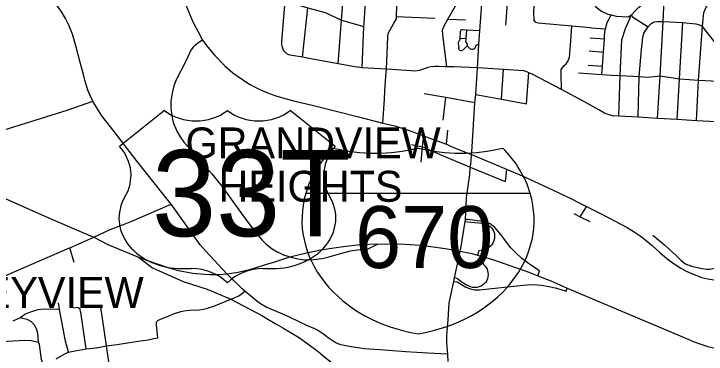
# Model space of a CAD drawing. Extents: x 1755200 to 1902939, y 644115 to 788070.
# Drawn here: x 1808159 to 1819343, y 715838 to 721334 of the extents above; entities that cross this region are included whole.
import ezdxf

# ---------------------------------------------------------------- set-up
doc = ezdxf.new("R2010")
doc.units = 0
for name, color, linetype in [('GM_X_City_Street', 7, 'Continuous'), ('GM_X_Corporation_Text', 7, 'Continuous'), ('GM_X_County_Road', 7, 'Continuous'), ('GM_X_Interchange_Ramps', 7, 'Continuous'), ('GM_X_Interstate_Route', 7, 'Continuous'), ('GM_X_Interstate_Shield', 7, 'Continuous'), ('GM_X_Township_Road', 7, 'Continuous'), ('GM_X_US_Route', 7, 'Continuous'), ('GM_X_US_Shield', 7, 'Continuous')]:
    doc.layers.add(name, color=color, linetype=linetype)

msp = doc.modelspace()

# ---------------------------------------------------------------- linework, layer by layer
at = {"layer": 'GM_X_City_Street'}
for points in [[(1813399, 720526), (1813451, 721233), (1813462, 721370), (1813547, 722431), (1813595, 723417)], [(1813818, 721182), (1813850, 721684), (1813883, 722187), (1813897, 722412), (1813959, 723379)], [(1816584, 721201), (1816564, 721229), (1816558, 721365), (1816571, 721550), (1816588, 721789), (1816595, 721883), (1816650, 722239), (1816678, 722540), (1816697, 722825), (1816713, 723063), (1816708, 723224)], [(1818559, 719644), (1818600, 720335), (1818648, 721210), (1818666, 721565), (1818619, 721791), (1818559, 722124), (1818551, 722245), (1818535, 722548), (1818544, 722781), (1818562, 723136)], [(1816109, 721151), (1816139, 721581), (1816162, 721906), (1816162, 721912), (1816202, 722264), (1816210, 722573), (1816230, 722857)], [(1815152, 720480), (1815091, 720998), (1815081, 721074), (1815119, 721161), (1815168, 721246), (1815293, 721465), (1815313, 721537), (1815344, 722283)], [(1815651, 720462), (1815662, 720643), (1815673, 720842), (1815689, 721058), (1815729, 721639), (1815751, 721965), (1815773, 722298), (1815773, 722298)], [(1809958, 719201), (1809777, 719434), (1809579, 719687), (1809497, 719814), (1809437, 719926), (1809398, 720003), (1809352, 720103), (1809304, 720261), (1809284, 720354), (1809233, 720551), (1809163, 720815), (1809107, 721004), (1809049, 721151), (1808995, 721259), (1808923, 721378), (1808795, 721558)], [(1814173, 720391), (1814173, 720391), (1814178, 720440), (1814200, 720961), (1814207, 721018), (1814300, 721182), (1814340, 721254), (1814342, 721293), (1814343, 721320), (1814356, 721651)], [(1815729, 721639), (1816139, 721581), (1816571, 721550), (1817069, 721516), (1817485, 721487), (1817541, 721482), (1817561, 721450), (1817650, 721377), (1817753, 721330), (1817809, 721316), (1817888, 721295), (1818085, 721284), (1818136, 721316), (1818155, 721285), (1818407, 721123), (1818447, 721175), (1818496, 721204), (1818544, 721213), (1818648, 721210), (1818967, 721193), (1819174, 721175), (1819235, 721155), (1819283, 721130)], [(1817930, 719683), (1817956, 720341), (1817979, 720913), (1818039, 721095), (1818136, 721316), (1818207, 721393), (1818257, 721444), (1818329, 721499), (1818410, 721560), (1818485, 721602)], [(1819188, 719608), (1819221, 720265), (1819283, 721130), (1819292, 721251), (1819303, 721357), (1819344, 721444), (1819364, 721476), (1819400, 721538), (1819441, 721589)], [(1812493, 720811), (1812492, 720811), (1812489, 720847), (1812489, 720885), (1812526, 721350), (1812544, 721530), (1812529, 721534)], [(1812544, 721530), (1812601, 721516), (1812779, 721467), (1812906, 721433), (1813130, 721374), (1813190, 721356), (1813451, 721233), (1813815, 721131)], [(1812820, 720634), (1812906, 721433)], [(1814342, 721293), (1814958, 721264)], [(1815168, 721246), (1815454, 721235)], [(1817698, 720924), (1817699, 720930), (1817702, 720974), (1817705, 721046), (1817714, 721091), (1817741, 721195), (1817776, 721254), (1817809, 721316)], [(1813786, 720462), (1813815, 721131), (1813817, 721162), (1813818, 721182)], [(1816584, 721201), (1816630, 721188), (1817173, 721139), (1817468, 721113), (1817489, 721111)], [(1817004, 720111), (1816998, 720373), (1817003, 720436), (1817042, 720492), (1817082, 720527), (1817113, 720573), (1817135, 720636), (1817142, 720692), (1817155, 720897), (1817173, 721139)], [(1817489, 721111), (1817714, 721091)], [(1818244, 719664), (1818261, 720320), (1818261, 720321), (1818296, 720759), (1818317, 720954), (1818338, 721024), (1818407, 721123)], [(1818874, 719627), (1818910, 720284), (1818967, 721193)], [(1819819, 719570), (1819833, 719890), (1819843, 720138), (1819831, 720229), (1819823, 720286), (1819788, 720414), (1819643, 720674), (1819283, 721130)], [(1815689, 721058), (1815471, 721072), (1815401, 721077), (1815388, 721077), (1815380, 721073), (1815375, 721067), (1815372, 721057), (1815370, 721047), (1815366, 720940), (1815364, 720919), (1815359, 720905), (1815349, 720891), (1815342, 720882), (1815338, 720873), (1815336, 720861), (1815339, 720849), (1815343, 720825), (1815346, 720812), (1815345, 720802), (1815343, 720785), (1815343, 720773), (1815346, 720764), (1815354, 720752), (1815372, 720742), (1815392, 720740), (1815407, 720745), (1815420, 720755), (1815482, 720819)], [(1815471, 721072), (1815461, 720935), (1815460, 720915), (1815457, 720891), (1815461, 720879), (1815471, 720861), (1815480, 720843), (1815482, 720819), (1815497, 720800), (1815524, 720777), (1815538, 720769), (1815554, 720765), (1815575, 720765), (1815590, 720770), (1815604, 720777), (1815613, 720790), (1815620, 720812), (1815629, 720830), (1815640, 720836), (1815654, 720839), (1815673, 720842)], [(1815366, 720940), (1815461, 720935)], [(1817471, 720949), (1817699, 720930)], [(1817660, 720357), (1817669, 720489), (1817684, 720714), (1817698, 720923), (1817698, 720924)], [(1815125, 720481), (1815023, 720483), (1814958, 720483), (1814894, 720479), (1814847, 720468), (1814803, 720453), (1814755, 720434), (1814710, 720420), (1814674, 720414), (1814630, 720411), (1814577, 720413), (1814178, 720440), (1813786, 720462), (1813669, 720479), (1813399, 720526), (1812958, 720610), (1812820, 720634), (1812621, 720666), (1812590, 720678), (1812570, 720690), (1812547, 720708), (1812531, 720728), (1812514, 720750), (1812503, 720779), (1812493, 720811)], [(1817452, 720736), (1817684, 720714)], [(1815651, 720462), (1815272, 720477), (1815152, 720480), (1815125, 720481)], [(1815621, 720025), (1815622, 720034), (1815651, 720462)], [(1820157, 719548), (1819819, 719570), (1819506, 719590), (1819188, 719608), (1818874, 719627), (1818559, 719644), (1818244, 719664), (1817930, 719683), (1817827, 719689), (1817776, 719701), (1817742, 719713), (1817703, 719732), (1817611, 719784), (1817369, 719918), (1817004, 720111), (1816531, 720358), (1816479, 720384), (1816445, 720399), (1816400, 720412), (1816068, 720437), (1815651, 720462)], [(1817435, 720507), (1817669, 720489)], [(1814158, 720175), (1814173, 720391)], [(1816039, 719957), (1816068, 720437)], [(1816442, 719879), (1816479, 720384)], [(1817278, 720383), (1817660, 720357), (1817815, 720346), (1817819, 720346)], [(1817819, 720346), (1817956, 720341), (1818261, 720320), (1818400, 720312), (1818600, 720335), (1818910, 720284), (1819070, 720275), (1819221, 720265), (1819536, 720245), (1819816, 720228), (1819831, 720229), (1819943, 720289), (1820166, 720333), (1820229, 720348)], [(1814147, 719955), (1814148, 719968), (1814158, 720175)], [(1815606, 719895), (1815135, 719984), (1814786, 720043)], [(1815557, 719102), (1815606, 719895), (1815610, 719948), (1815621, 720025)], [(1815622, 720034), (1816039, 719957), (1816442, 719879)], [(1807147, 719191), (1807170, 719199), (1807985, 719456), (1809018, 719781), (1809437, 719926)], [(1814122, 719571), (1814147, 719955)], [(1815096, 719617), (1815135, 719984)], [(1815146, 719227), (1815167, 719455)], [(1814740, 718940), (1814763, 719186), (1814781, 719365)], [(1814583, 719226), (1814763, 719186), (1815133, 719023), (1815430, 718902)], [(1810572, 718422), (1810424, 718606), (1810134, 718972), (1809988, 719162), (1809958, 719201)], [(1815539, 718908), (1815545, 718962), (1815554, 719061), (1815557, 719102)], [(1815360, 717443), (1815371, 717499), (1815382, 717545), (1815451, 717980), (1815454, 717999), (1815455, 718015), (1815473, 718369), (1815524, 718736), (1815533, 718860), (1815539, 718908)], [(1815430, 718902), (1815533, 718860), (1816095, 718628)], [(1816118, 718825), (1816095, 718628)], [(1810703, 718260), (1810703, 718260), (1810572, 718422)], [(1806605, 716759), (1807192, 716801), (1807332, 716813), (1807406, 716833), (1807662, 716944), (1808163, 717165), (1809059, 717554), (1809064, 717556), (1809453, 717726), (1809714, 717849), (1809933, 717932), (1810065, 717987), (1810703, 718260)], [(1811623, 717114), (1811601, 717134), (1811262, 717499), (1811169, 717604), (1810703, 718260)], [(1817310, 718056), (1817410, 718217)], [(1817203, 718109), (1817310, 718056), (1817461, 717980)], [(1818481, 717762), (1818673, 717599), (1818861, 717425), (1818939, 717353), (1818973, 717323), (1819008, 717298), (1819048, 717279), (1819069, 717273)], [(1809135, 717320), (1809064, 717556)], [(1815266, 717013), (1815278, 717070), (1815344, 717364), (1815360, 717443)], [(1819069, 717273), (1819108, 717261), (1819274, 717221), (1819353, 717213), (1819398, 717213), (1819488, 717227), (1819611, 717251), (1819727, 717269), (1819832, 717280), (1819894, 717283), (1819967, 717285), (1820035, 717283), (1820131, 717271), (1820208, 717254)], [(1811849, 716894), (1811623, 717114)], [(1815173, 715717), (1815167, 715834), (1815156, 716028), (1815156, 716120), (1815160, 716213), (1815173, 716390), (1815193, 716667), (1815266, 717013)], [(1814849, 715853), (1814492, 715873), (1814073, 715906), (1813816, 715923), (1813577, 715960), (1813497, 715978), (1813439, 715990), (1813400, 716003), (1813360, 716019), (1813300, 716057), (1813270, 716078), (1813236, 716104), (1813188, 716140), (1813145, 716170), (1813115, 716193), (1813086, 716211), (1813051, 716230), (1813019, 716245), (1812985, 716262), (1812940, 716281), (1812801, 716344), (1812734, 716375), (1812530, 716471), (1812237, 716596), (1812144, 716649), (1812082, 716691), (1812013, 716755), (1811888, 716856), (1811849, 716894)], [(1810674, 716463), (1810690, 716470), (1810739, 716490), (1810854, 716524), (1810905, 716535), (1810996, 716546), (1811153, 716553), (1811221, 716563), (1811287, 716581), (1811392, 716611), (1811663, 716726), (1811746, 716759), (1811792, 716782), (1811833, 716807), (1811888, 716856)], [(1809043, 715868), (1809011, 715988), (1808995, 716046), (1808895, 716561), (1808881, 716668)], [(1808147, 716377), (1808258, 716424), (1808335, 716483), (1808402, 716512), (1808480, 716538), (1808551, 716561), (1808645, 716568), (1808756, 716566), (1808841, 716571), (1808895, 716561)], [(1809239, 716514), (1809238, 716519), (1809228, 716562), (1809195, 716590), (1809162, 716588), (1809125, 716582)], [(1808631, 715670), (1808605, 715754), (1808572, 715995), (1808558, 716030), (1808544, 716176), (1808524, 716248), (1808494, 716307), (1808446, 716361), (1808374, 716399), (1808258, 716424)], [(1809327, 715923), (1809239, 716514)], [(1806795, 715920), (1806834, 715930), (1806904, 715944), (1806960, 715951), (1807011, 715952), (1807047, 715948), (1807085, 715936), (1807203, 715903), (1807311, 715863), (1807379, 715846), (1807447, 715841), (1807486, 715850), (1807559, 715890), (1807651, 715939), (1807726, 715976), (1807823, 716013), (1807967, 716042), (1808146, 716054), (1808338, 716066), (1808432, 716056), (1808558, 716030)], [(1808844, 715764), (1808983, 715842), (1809043, 715868), (1809091, 715882), (1809151, 715894), (1809327, 715923), (1809485, 715941), (1809495, 715942)], [(1815164, 715835), (1814849, 715853)]]:
    msp.add_lwpolyline(points, dxfattribs=at)
at = {"layer": 'GM_X_County_Road'}
for points in [[(1809495, 715942), (1809655, 715970), (1809830, 715992), (1809997, 716020), (1810170, 716045), (1810330, 716067), (1810415, 716088), (1810484, 716101), (1810463, 716319), (1810462, 716342), (1810466, 716353), (1810471, 716364), (1810485, 716381), (1810496, 716389), (1810520, 716398), (1810665, 716459), (1810674, 716463)], [(1809725, 715494), (1809655, 715970)]]:
    msp.add_lwpolyline(points, dxfattribs=at)
at = {"layer": 'GM_X_Interchange_Ramps'}
for points in [[(1815451, 717980), (1815495, 717975), (1815718, 717954), (1815756, 717949), (1815790, 717939), (1815824, 717921), (1815856, 717898), (1815879, 717872), (1815896, 717847), (1815911, 717818), (1815921, 717784), (1815926, 717748), (1815925, 717719), (1815920, 717687), (1815910, 717656), (1815897, 717629), (1815881, 717605), (1815859, 717581), (1815833, 717560), (1815804, 717543), (1815780, 717533), (1815752, 717525), (1815727, 717517), (1815668, 717509), (1815648, 717438)], [(1816626, 717105), (1816652, 717182), (1816544, 717253), (1816453, 717316), (1816367, 717384), (1816262, 717481), (1816182, 717558), (1816025, 717769), (1815928, 717886), (1815851, 717940), (1815783, 717969), (1815723, 717980), (1815489, 718011), (1815455, 718015)], [(1815691, 717427), (1815671, 717350), (1815727, 717313), (1815748, 717285), (1815769, 717264), (1815787, 717240), (1815803, 717209), (1815813, 717182), (1815818, 717154), (1815820, 717125), (1815817, 717089), (1815808, 717054), (1815798, 717030), (1815781, 717003), (1815761, 716978), (1815735, 716955), (1815706, 716937), (1815675, 716924), (1815640, 716915), (1815600, 716913), (1815568, 716916), (1815539, 716924), (1815482, 716946), (1815399, 716996), (1815360, 717026), (1815318, 717061), (1815278, 717070)], [(1815266, 717013), (1815323, 717005), (1815460, 716922), (1815534, 716891), (1815602, 716876), (1815683, 716875), (1816387, 716954), (1816507, 716962), (1816612, 716956), (1816684, 716951), (1816809, 716928), (1816923, 716902), (1817083, 716857), (1817100, 716906)]]:
    msp.add_lwpolyline(points, dxfattribs=at)
at = {"layer": 'GM_X_Interstate_Route'}
for points in [[(1806655, 718911), (1806844, 718852), (1807027, 718784), (1807630, 718532), (1807973, 718373), (1808709, 718045), (1809282, 717799)], [(1809282, 717799), (1809453, 717726), (1809678, 717611), (1809923, 717505), (1810172, 717404)], [(1813076, 717514), (1813084, 717515), (1813328, 717556), (1813485, 717579), (1813749, 717607), (1814045, 717621)], [(1814045, 717621), (1814476, 717615), (1814729, 717598), (1814975, 717567), (1815128, 717544), (1815288, 717519), (1815371, 717499), (1815556, 717461), (1815648, 717438), (1815691, 717427), (1815890, 717365)], [(1812194, 717274), (1812392, 717335), (1812616, 717407), (1812887, 717474), (1813076, 717514)], [(1810172, 717404), (1810400, 717234), (1810892, 717013), (1811280, 716889), (1811284, 716887)], [(1810172, 717404), (1810318, 717348), (1810457, 717300), (1810663, 717232), (1810821, 717188), (1811048, 717144), (1811232, 717129), (1811323, 717125), (1811419, 717125), (1811489, 717126), (1811601, 717134), (1811785, 717163), (1811989, 717210), (1812194, 717274)], [(1815890, 717365), (1815957, 717344), (1816479, 717163), (1816626, 717105), (1816835, 717020), (1816977, 716959), (1817100, 716906), (1818679, 716237), (1819026, 716088), (1819149, 716037), (1819242, 716003), (1819371, 715962), (1819459, 715940), (1819560, 715923), (1819658, 715911), (1819746, 715906), (1819870, 715906), (1819979, 715916), (1820051, 715924), (1820124, 715937), (1820203, 715956), (1820259, 715970), (1820338, 715996)], [(1811284, 716887), (1811663, 716726), (1812165, 716461), (1812261, 716404)], [(1812261, 716404), (1812389, 716328), (1812504, 716265), (1812533, 716247)], [(1812533, 716247), (1812678, 716161), (1812775, 716100), (1812908, 716002), (1813077, 715880), (1813183, 715790), (1813411, 715611), (1813749, 715304), (1814209, 714873), (1814376, 714732), (1814645, 714472), (1814906, 714207), (1815133, 713987), (1815483, 713571), (1815623, 713399), (1815769, 713210)]]:
    msp.add_lwpolyline(points, dxfattribs=at)
at = {"layer": 'GM_X_Interstate_Shield'}
msp.add_line((1816501, 718433), (1812875, 718433), dxfattribs=at)
msp.add_line((1816501, 718433), (1812875, 718433), dxfattribs=at)
for centre, start_param, end_param in [((1815157, 718004), 2.47259, 2.911027), ((1814003, 720960), 4.415841, 5.008937), ((1815373, 720960), 4.415841, 5.008937), ((1814219, 718004), 0.230566, 0.669003), ((1815157, 718004), 2.911027, 4.511031), ((1814219, 718004), 4.913747, 6.513751)]:
    msp.add_ellipse(centre, major_axis=(2344, 0), ratio=0.8, start_param=start_param, end_param=end_param, dxfattribs=at)
at = {"layer": 'GM_X_Township_Road'}
msp.add_lwpolyline([(1809655, 715970), (1809561, 716635)], dxfattribs=at)
at = {"layer": 'GM_X_US_Route'}
for points in [[(1810310, 723017), (1810464, 722633), (1810581, 722350), (1810762, 721905), (1810941, 721465), (1811022, 721271), (1811074, 721163), (1811136, 721044), (1811208, 720910)], [(1811208, 720910), (1811130, 720860), (1811054, 720798), (1811020, 720745), (1810969, 720640)], [(1811208, 720910), (1811295, 720795), (1811406, 720663), (1811570, 720494), (1811699, 720383), (1811851, 720274), (1811921, 720228), (1811979, 720194), (1812037, 720160), (1812146, 720105), (1812275, 720052), (1812392, 720012), (1812518, 719973), (1812699, 719926), (1812958, 719863), (1813364, 719763), (1813703, 719677), (1814122, 719571), (1814315, 719525), (1814545, 719452), (1814781, 719365), (1814864, 719334), (1815146, 719227), (1815215, 719198), (1815467, 719095), (1815509, 719079)], [(1810969, 720640), (1810924, 720550), (1810788, 720277), (1810746, 720169), (1810721, 720080), (1810707, 719993), (1810697, 719916), (1810696, 719825), (1810701, 719760), (1810709, 719704), (1810717, 719656), (1810730, 719605), (1810745, 719554), (1810769, 719493), (1810799, 719429), (1810845, 719346), (1810904, 719263), (1811006, 719146), (1811155, 718969), (1811246, 718872), (1811359, 718748), (1811429, 718662)], [(1815509, 719079), (1815554, 719061)], [(1815554, 719061), (1816118, 718825), (1816410, 718700), (1816793, 718523), (1817146, 718355), (1817314, 718270)], [(1811429, 718662), (1811519, 718550), (1811793, 718171), (1811941, 717968), (1812082, 717780), (1812163, 717686), (1812236, 717612), (1812331, 717541), (1812426, 717487), (1812462, 717467), (1812501, 717448), (1812616, 717407), (1812748, 717375), (1812855, 717363), (1812923, 717363), (1813000, 717364), (1813140, 717385), (1813248, 717409), (1813457, 717468), (1813600, 717504), (1813713, 717524), (1813881, 717541), (1814045, 717621)], [(1817314, 718270), (1817441, 718207), (1817644, 718102), (1817874, 717985), (1818069, 717882), (1818182, 717816), (1818276, 717751), (1818349, 717695), (1818473, 717591), (1818596, 717481), (1818714, 717377), (1818714, 717377)], [(1818714, 717377), (1818841, 717285), (1818933, 717228), (1819022, 717179), (1819124, 717133), (1819273, 717078), (1819367, 717054), (1819436, 717041), (1820071, 716937), (1820216, 716923), (1820291, 716920)]]:
    msp.add_lwpolyline(points, dxfattribs=at)
at = {"layer": 'GM_X_US_Shield'}
for p, q in [((1810593, 719772), (1809868, 719192)), ((1813349, 719192), (1812623, 719772)), ((1810883, 717220), (1811028, 717220)), ((1812188, 717220), (1812333, 717220))]:
    msp.add_line(p, q, dxfattribs=at)
for centre, major_axis, start_param, end_param in [((1811101, 720186), (-725, 0), 0.795399, 2.346194), ((1812116, 720186), (-725, 0), 0.795399, 2.346194), ((1809037, 718726), (1015, 0), 5.838949, 6.894067), ((1814180, 718726), (-1015, 0), 5.672304, 6.727422), ((1810872, 718032), (1015, 0), 2.702327, 4.723529), ((1812345, 718032), (-1015, 0), 1.559657, 3.580859), ((1811028, 716640), (-725, 0), 3.785094, 4.712389), ((1812188, 716640), (-725, 0), 4.712389, 5.639684)]:
    msp.add_ellipse(centre, major_axis=major_axis, ratio=0.8, start_param=start_param, end_param=end_param, dxfattribs=at)

# ---------------------------------------------------------------- texts
at = {"layer": 'GM_X_Corporation_Text'}
for s, p in [('GRANDVIEW', (1810931, 718999)), ('HEIGHTS', (1811465, 718299)), ('VALLEYVIEW', (1806020, 716583))]:
    msp.add_text(s, height=500, rotation=0, dxfattribs=at).set_placement(p)
at = {"layer": 'GM_X_Interstate_Shield'}
msp.add_text('670', height=1000, dxfattribs=at).set_placement((1813672, 717229))
at = {"layer": 'GM_X_US_Shield'}
msp.add_text('33T', height=1392.2, dxfattribs=at).set_placement((1810391, 717742))

doc.saveas('drawing.dxf')
